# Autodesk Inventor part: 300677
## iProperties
Created: 2007-11
Part Number: 300677
Document SubType Name: Modeling
Designer: TH
Density: 8.08 g/cm^3
Mass: 81.1085 g
Surface Area: 92.7417 cm^2
Volume: 10.0382 cm^3
Material: Stainless Steel
Description: RIGHT BACK WIRE
Component Category: Back Component
Author: TH
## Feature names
1. Sweep1
2. Sweep2
3. Sweep3
4. Sweep4
5. Sweep5
